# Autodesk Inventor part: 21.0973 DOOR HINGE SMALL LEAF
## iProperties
Created: 2007-01
Part Number: 21.0973 DOOR HINGE SMALL LEAF
Document SubType Name: Modeling
Designer: Andy Moles
Material: Aluminum-6061
Density: 2.71 g/cm^3
Author: Andy Moles
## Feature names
1. Extrusion1
2. Extrusion2
3. Hole1
